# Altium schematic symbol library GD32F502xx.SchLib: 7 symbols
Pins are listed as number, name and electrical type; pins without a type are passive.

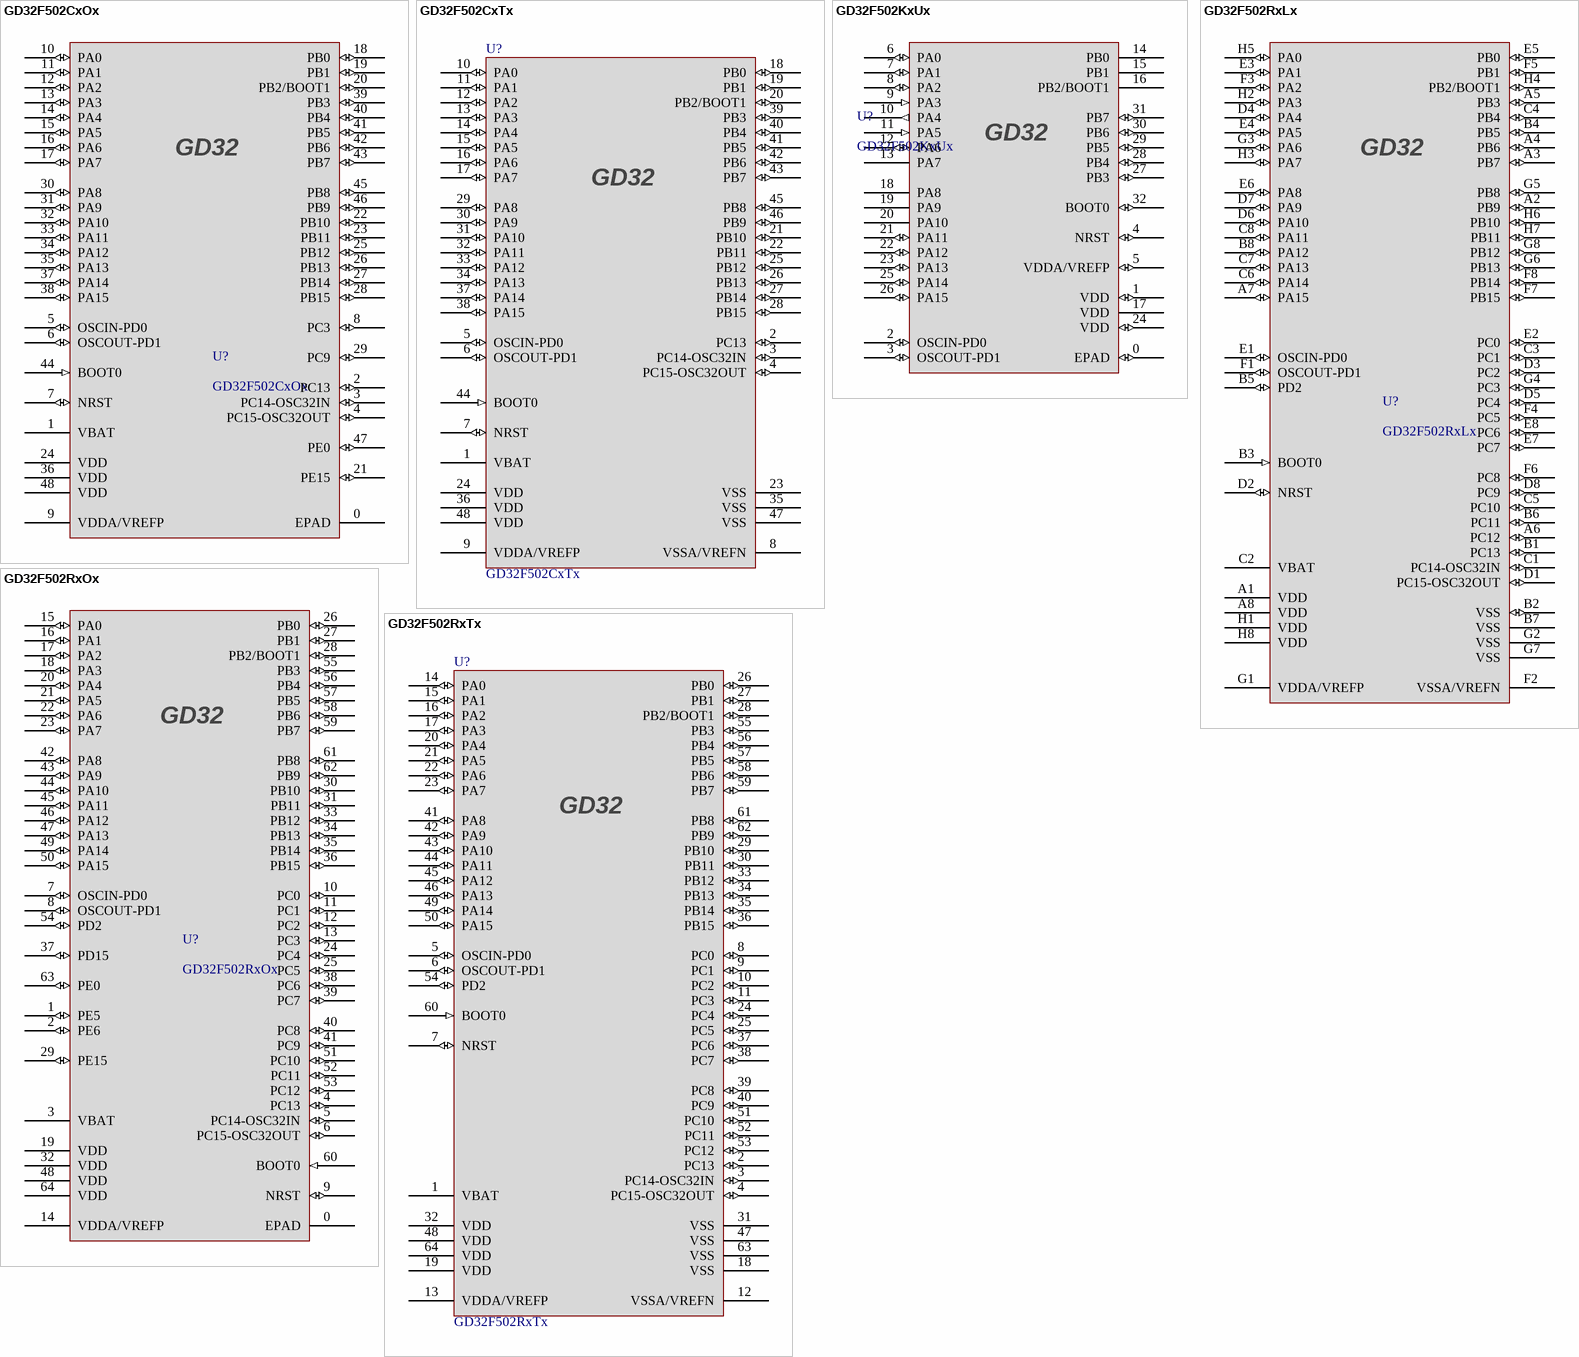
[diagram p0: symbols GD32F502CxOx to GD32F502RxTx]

## GD32F502CxOx
designator U?
footprint QFN48_5X5X0.8
pins: 0 EPAD (power), 1 VBAT (power), 2 PC13 (io), 3 PC14-OSC32IN (io), 4 PC15-OSC32OUT (io), 5 OSCIN-PD0 (io), 6 OSCOUT-PD1 (io), 7 NRST (io), 8 PC3 (io), 9 VDDA/VREFP (power), 10 PA0 (io), 11 PA1 (io), 12 PA2 (io), 13 PA3 (io), 14 PA4 (io), 15 PA5 (io), 16 PA6 (io), 17 PA7 (io), 18 PB0 (io), 19 PB1 (io), 20 PB2/BOOT1 (io), 21 PE15 (io), 22 PB10 (io), 23 PB11 (io), 24 VDD (power), 25 PB12 (io), 26 PB13 (io), 27 PB14 (io), 28 PB15 (io), 29 PC9 (io), 30 PA8 (io), 31 PA9 (io), 32 PA10 (io), 33 PA11 (io), 34 PA12 (io), 35 PA13 (io), 36 VDD (power), 37 PA14 (io), 38 PA15 (io), 39 PB3 (io), 40 PB4 (io), 41 PB5 (io), 42 PB6 (io), 43 PB7 (io), 44 BOOT0 (in), 45 PB8 (io), 46 PB9 (io), 47 PE0 (io), 48 VDD (power)

## GD32F502CxTx
designator U?
footprint LQFP48_7x7x1.6
pins: 1 VBAT (power), 2 PC13 (io), 3 PC14-OSC32IN (io), 4 PC15-OSC32OUT (io), 5 OSCIN-PD0 (io), 6 OSCOUT-PD1 (io), 7 NRST (io), 8 VSSA/VREFN (power), 9 VDDA/VREFP (power), 10 PA0 (io), 11 PA1 (io), 12 PA2 (io), 13 PA3 (io), 14 PA4 (io), 15 PA5 (io), 16 PA6 (io), 17 PA7 (io), 18 PB0 (io), 19 PB1 (io), 20 PB2/BOOT1 (io), 21 PB10 (io), 22 PB11 (io), 23 VSS (power), 24 VDD (power), 25 PB12 (io), 26 PB13 (io), 27 PB14 (io), 28 PB15 (io), 29 PA8 (io), 30 PA9 (io), 31 PA10 (io), 32 PA11 (io), 33 PA12 (io), 34 PA13 (io), 35 VSS (power), 36 VDD (power), 37 PA14 (io), 38 PA15 (io), 39 PB3 (io), 40 PB4 (io), 41 PB5 (io), 42 PB6 (io), 43 PB7 (io), 44 BOOT0 (in), 45 PB8 (io), 46 PB9 (io), 47 VSS (power), 48 VDD (power)
2 alternate drawings of the same symbol

## GD32F502KxUx
designator U?
footprint QFN32_5X5X0.8
pins: 0 EPAD (io), 1 VDD (io), 2 OSCIN-PD0 (io), 3 OSCOUT-PD1 (io), 4 NRST (io), 5 VDDA/VREFP (io), 6 PA0 (io), 7 PA1 (io), 8 PA2 (io), 9 PA3 (in), 10 PA4 (out), 11 PA5 (in), 12 PA6 (io), 13 PA7 (power), 14 PB0 (power), 15 PB1 (power), 16 PB2/BOOT1 (power), 17 VDD (power), 18 PA8 (power), 19 PA9 (power), 20 PA10 (power), 21 PA11 (io), 22 PA12 (io), 23 PA13 (io), 24 VDD (io), 25 PA14 (io), 26 PA15 (io), 27 PB3 (io), 28 PB4 (io), 29 PB5 (io), 30 PB6 (io), 31 PB7 (io), 32 BOOT0 (io)

## GD32F502RxLx
designator U?
footprint BGA64_4x4X0.84
pins: A1 VDD (power), A2 PB9 (io), A3 PB7 (io), A4 PB6 (io), A5 PB3 (io), A6 PC12 (io), A7 PA15 (io), A8 VDD (power), B1 PC13 (io), B2 VSS (io), B3 BOOT0 (in), B4 PB5 (io), B5 PD2 (io), B6 PC11 (io), B7 VSS (power), B8 PA12 (io), C1 PC14-OSC32IN (io), C2 VBAT (power), C3 PC1 (io), C4 PB4 (io), C5 PC10 (io), C6 PA14 (io), C7 PA13 (io), C8 PA11 (io), D1 PC15-OSC32OUT (io), D2 NRST (io), D3 PC2 (io), D4 PA4 (io), D5 PC4 (io), D6 PA10 (io), D7 PA9 (io), D8 PC9 (io), E1 OSCIN-PD0 (io), E2 PC0 (io), E3 PA1 (io), E4 PA5 (io), E5 PB0 (io), E6 PA8 (io), E7 PC7 (io), E8 PC6 (io), F1 OSCOUT-PD1 (io), F2 VSSA/VREFN (power), F3 PA2 (io), F4 PC5 (io), F5 PB1 (io), F6 PC8 (io), F7 PB15 (io), F8 PB14 (io), G1 VDDA/VREFP (power), G2 VSS (power), G3 PA6 (io), G4 PC3 (io), G5 PB8 (io), G6 PB13 (io), G7 VSS (power), G8 PB12 (io), H1 VDD (power), H2 PA3 (io), H3 PA7 (io), H4 PB2/BOOT1 (io), H5 PA0 (io), H6 PB10 (io), H7 PB11 (io), H8 VDD (power)

## GD32F502RxOx
designator U?
footprint QFN64_7X7X0.8
pins: 0 EPAD (power), 1 PE5 (io), 2 PE6 (io), 3 VBAT (power), 4 PC13 (io), 5 PC14-OSC32IN (io), 6 PC15-OSC32OUT (io), 7 OSCIN-PD0 (io), 8 OSCOUT-PD1 (io), 9 NRST (io), 10 PC0 (io), 11 PC1 (io), 12 PC2 (io), 13 PC3 (io), 14 VDDA/VREFP (power), 15 PA0 (io), 16 PA1 (io), 17 PA2 (io), 18 PA3 (io), 19 VDD (power), 20 PA4 (io), 21 PA5 (io), 22 PA6 (io), 23 PA7 (io), 24 PC4 (io), 25 PC5 (io), 26 PB0 (io), 27 PB1 (io), 28 PB2/BOOT1 (io), 29 PE15 (io), 30 PB10 (io), 31 PB11 (io), 32 VDD (power), 33 PB12 (io), 34 PB13 (io), 35 PB14 (io), 36 PB15 (io), 37 PD15 (io), 38 PC6 (io), 39 PC7 (io), 40 PC8 (io), 41 PC9 (io), 42 PA8 (io), 43 PA9 (io), 44 PA10 (io), 45 PA11 (io), 46 PA12 (io), 47 PA13 (io), 48 VDD (power), 49 PA14 (io), 50 PA15 (io), 51 PC10 (io), 52 PC11 (io), 53 PC12 (io), 54 PD2 (io), 55 PB3 (io), 56 PB4 (io), 57 PB5 (io), 58 PB6 (io), 59 PB7 (io), 60 BOOT0 (in), 61 PB8 (io), 62 PB9 (io), 63 PE0 (io), 64 VDD (power)

## GD32F502RxTx
designator U?
footprint LQPF64_10x10x1.6
pins: 1 VBAT (power), 2 PC13 (io), 3 PC14-OSC32IN (io), 4 PC15-OSC32OUT (io), 5 OSCIN-PD0 (io), 6 OSCOUT-PD1 (io), 7 NRST (io), 8 PC0 (io), 9 PC1 (io), 10 PC2 (io), 11 PC3 (io), 12 VSSA/VREFN (power), 13 VDDA/VREFP (power), 14 PA0 (io), 15 PA1 (io), 16 PA2 (io), 17 PA3 (io), 18 VSS (power), 19 VDD (power), 20 PA4 (io), 21 PA5 (io), 22 PA6 (io), 23 PA7 (io), 24 PC4 (io), 25 PC5 (io), 26 PB0 (io), 27 PB1 (io), 28 PB2/BOOT1 (io), 29 PB10 (io), 30 PB11 (io), 31 VSS (power), 32 VDD (power), 33 PB12 (io), 34 PB13 (io), 35 PB14 (io), 36 PB15 (io), 37 PC6 (io), 38 PC7 (io), 39 PC8 (io), 40 PC9 (io), 41 PA8 (io), 42 PA9 (io), 43 PA10 (io), 44 PA11 (io), 45 PA12 (io), 46 PA13 (io), 47 VSS (power), 48 VDD (power), 49 PA14 (io), 50 PA15 (io), 51 PC10 (io), 52 PC11 (io), 53 PC12 (io), 54 PD2 (io), 55 PB3 (io), 56 PB4 (io), 57 PB5 (io), 58 PB6 (io), 59 PB7 (io), 60 BOOT0 (in), 61 PB8 (io), 62 PB9 (io), 63 VSS (power), 64 VDD (power)
2 alternate drawings of the same symbol

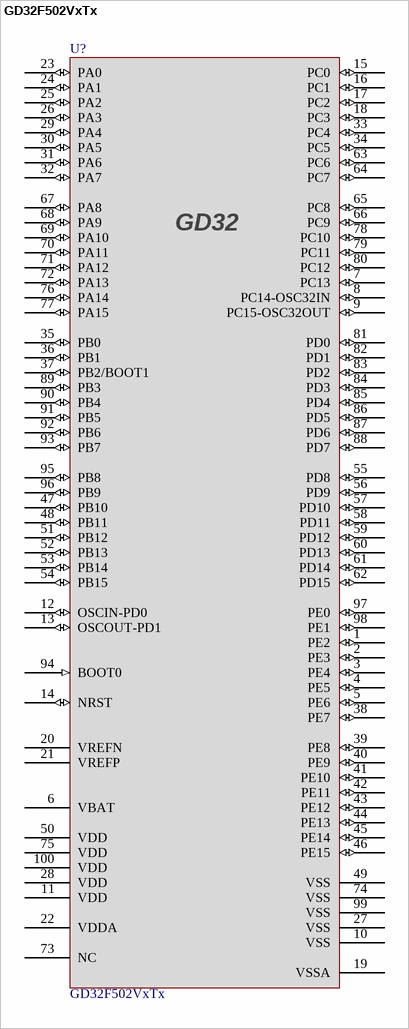
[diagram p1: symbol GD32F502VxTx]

## GD32F502VxTx
designator U?
footprint LQFP100_14x14x1.6
pins: 1 PE2 (io), 2 PE3 (io), 3 PE4 (io), 4 PE5 (io), 5 PE6 (io), 6 VBAT (power), 7 PC13 (io), 8 PC14-OSC32IN (io), 9 PC15-OSC32OUT (io), 10 VSS (power), 11 VDD (power), 12 OSCIN-PD0 (io), 13 OSCOUT-PD1 (io), 14 NRST (io), 15 PC0 (io), 16 PC1 (io), 17 PC2 (io), 18 PC3 (io), 19 VSSA (power), 20 VREFN (power), 21 VREFP (power), 22 VDDA (power), 23 PA0 (io), 24 PA1 (io), 25 PA2 (io), 26 PA3 (io), 27 VSS (power), 28 VDD (power), 29 PA4 (io), 30 PA5 (io), 31 PA6 (io), 32 PA7 (io), 33 PC4 (io), 34 PC5 (io), 35 PB0 (io), 36 PB1 (io), 37 PB2/BOOT1 (io), 38 PE7 (io), 39 PE8 (io), 40 PE9 (io), 41 PE10 (io), 42 PE11 (io), 43 PE12 (io), 44 PE13 (io), 45 PE14 (io), 46 PE15 (io), 47 PB10 (io), 48 PB11 (io), 49 VSS (power), 50 VDD (power), 51 PB12 (io), 52 PB13 (io), 53 PB14 (io), 54 PB15 (io), 55 PD8 (io), 56 PD9 (io), 57 PD10 (io), 58 PD11 (io), 59 PD12 (io), 60 PD13 (io), 61 PD14 (io), 62 PD15 (io), 63 PC6 (io), 64 PC7 (io), 65 PC8 (io), 66 PC9 (io), 67 PA8 (io), 68 PA9 (io), 69 PA10 (io), 70 PA11 (io), 71 PA12 (io), 72 PA13 (io), 73 NC, 74 VSS (power), 75 VDD (power), 76 PA14 (io), 77 PA15 (io), 78 PC10 (io), 79 PC11 (io), 80 PC12 (io), 81 PD0 (io), 82 PD1 (io), 83 PD2 (io), 84 PD3 (io), 85 PD4 (io), 86 PD5 (io), 87 PD6 (io), 88 PD7 (io), 89 PB3 (io), 90 PB4 (io), 91 PB5 (io), 92 PB6 (io), 93 PB7 (io), 94 BOOT0 (in), 95 PB8 (io), 96 PB9 (io), 97 PE0 (io), 98 PE1 (io), 99 VSS (power), 100 VDD (power)
2 alternate drawings of the same symbol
